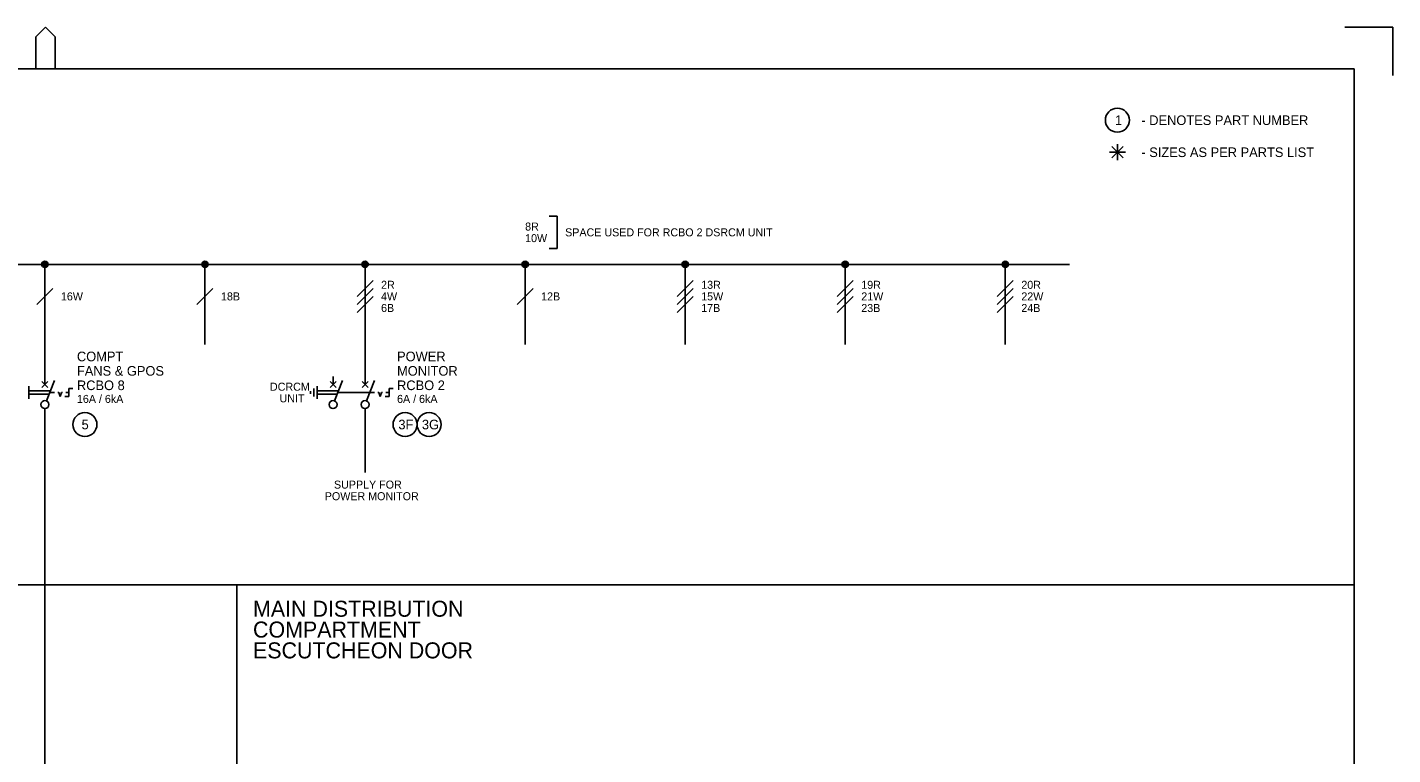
# Model space of a CAD drawing. Extents: x 0 to 841, y 0 to 594.
# Drawn here: x 414.5 to 841, y 366.9 to 594 of the extents above; entities that cross this region are included whole.
import ezdxf

# ---------------------------------------------------------------- set-up
doc = ezdxf.new("R2010")
doc.units = 0
for name, color, linetype in [('A1BORDER', 7, 'Continuous'), ('Level 1', 7, 'Continuous'), ('Level 10', 7, 'Continuous')]:
    doc.layers.add(name, color=color, linetype=linetype)

msp = doc.modelspace()

# ---------------------------------------------------------------- linework, layer by layer
at = {"layer": 'A1BORDER'}
for p, q in [((417.19, 591), (420.19, 594)), ((423.19, 591), (420.19, 594)), ((826, 594), (841, 594)), ((841, 579), (841, 594)), ((417.19, 581), (417.19, 591)), ((423.19, 581), (423.19, 591)), ((28, 581), (829, 581)), ((829, 581), (829, 15))]:
    msp.add_line(p, q, dxfattribs=at)
at = {"layer": 'Level 1'}
for p, q in [((752.5, 555), (757.5, 555)), ((753.23, 556.77), (756.77, 553.23)), ((753.23, 553.23), (756.77, 556.77)), ((755, 552.5), (755, 557.5)), ((80, 520), (740, 520)), ((420, 520), (420, 485)), ((470, 520), (470, 495)), ((520, 520), (520, 485)), ((570, 520), (570, 495)), ((620, 520), (620, 495)), ((670, 520), (670, 495)), ((720, 520), (720, 495)), ((417.5, 507.5), (422.5, 512.5)), ((467.5, 507.5), (472.5, 512.5)), ((517.5, 510), (522.5, 515)), ((517.5, 507.5), (522.5, 512.5)), ((567.5, 507.5), (572.5, 512.5)), ((617.5, 510), (622.5, 515)), ((617.5, 507.5), (622.5, 512.5)), ((667.5, 510), (672.5, 515)), ((667.5, 507.5), (672.5, 512.5)), ((717.5, 510), (722.5, 515)), ((717.5, 507.5), (722.5, 512.5)), ((517.5, 505), (522.5, 510)), ((617.5, 505), (622.5, 510)), ((667.5, 505), (672.5, 510)), ((717.5, 505), (722.5, 510)), ((419.06, 483.44), (420.94, 481.56)), ((420.94, 483.44), (419.06, 481.56)), ((420, 482.5), (420, 485)), ((420.46, 477.41), (423, 483.75)), ((509.06, 483.44), (510.94, 481.56)), ((510.94, 483.44), (509.06, 481.56)), ((510, 482.5), (510, 485)), ((510.46, 477.41), (513, 483.75)), ((519.06, 483.44), (520.94, 481.56)), ((520.94, 483.44), (519.06, 481.56)), ((520, 482.5), (520, 485)), ((520.46, 477.41), (523, 483.75)), ((415, 480.5), (421.7, 480.5)), ((415, 479.5), (421.3, 479.5)), ((505, 480.5), (511.7, 480.5)), ((505, 479.5), (511.3, 479.5)), ((511.5, 480), (521.5, 480)), ((420, 475), (420, 105)), ((520, 475), (520, 455)), ((829, 420), (28, 420)), ((480, 420), (480, 57))]:
    msp.add_line(p, q, dxfattribs=at)
msp.add_lwpolyline([(577.5, 535), (580, 535), (580, 525), (577.5, 525)], dxfattribs=at)
for centre, radius in [((755, 565), 3.75), ((420, 476.25), 1.25), ((432.5, 470), 3.75), ((510, 476.25), 1.25), ((520, 476.25), 1.25), ((532.5, 470), 3.75), ((540, 470), 3.75)]:
    msp.add_circle(centre, radius, dxfattribs=at)
at = {"layer": 'Level 10'}
for p, q in [((419.08, 520.4), (420.92, 520.4)), ((419.29, 520.7), (420.71, 520.7)), ((420, 521), (420, 521)), ((469.08, 520.4), (470.92, 520.4)), ((469.29, 520.7), (470.71, 520.7)), ((470, 521), (470, 521)), ((519.08, 520.4), (520.92, 520.4)), ((519.29, 520.7), (520.71, 520.7)), ((520, 521), (520, 521)), ((569.08, 520.4), (570.92, 520.4)), ((569.29, 520.7), (570.71, 520.7)), ((570, 521), (570, 521)), ((619.08, 520.4), (620.92, 520.4)), ((619.29, 520.7), (620.71, 520.7)), ((620, 521), (620, 521)), ((669.08, 520.4), (670.92, 520.4)), ((669.29, 520.7), (670.71, 520.7)), ((670, 521), (670, 521)), ((719.08, 520.4), (720.92, 520.4)), ((719.29, 520.7), (720.71, 520.7)), ((720, 521), (720, 521)), ((419.01, 520.1), (420.99, 520.1)), ((419.02, 519.8), (420.98, 519.8)), ((419.13, 519.5), (420.87, 519.5)), ((419.4, 519.2), (420.6, 519.2)), ((469.01, 520.1), (470.99, 520.1)), ((469.02, 519.8), (470.98, 519.8)), ((469.13, 519.5), (470.87, 519.5)), ((469.4, 519.2), (470.6, 519.2)), ((519.01, 520.1), (520.99, 520.1)), ((519.02, 519.8), (520.98, 519.8)), ((519.13, 519.5), (520.87, 519.5)), ((519.4, 519.2), (520.6, 519.2)), ((569.01, 520.1), (570.99, 520.1)), ((569.02, 519.8), (570.98, 519.8)), ((569.13, 519.5), (570.87, 519.5)), ((569.4, 519.2), (570.6, 519.2)), ((619.01, 520.1), (620.99, 520.1)), ((619.02, 519.8), (620.98, 519.8)), ((619.13, 519.5), (620.87, 519.5)), ((619.4, 519.2), (620.6, 519.2)), ((669.01, 520.1), (670.99, 520.1)), ((669.02, 519.8), (670.98, 519.8)), ((669.13, 519.5), (670.87, 519.5)), ((669.4, 519.2), (670.6, 519.2)), ((719.01, 520.1), (720.99, 520.1)), ((719.02, 519.8), (720.98, 519.8)), ((719.13, 519.5), (720.87, 519.5)), ((719.4, 519.2), (720.6, 519.2)), ((415, 482), (415, 478)), ((505, 482), (505, 478)), ((421.5, 480), (423, 480)), ((424, 480), (424.33, 480)), ((424.75, 478.75), (424.33, 480)), ((424.75, 478.75), (425.17, 480)), ((425.5, 480), (425.17, 480)), ((426.25, 478.75), (427.5, 478.75)), ((426.5, 480), (427.5, 480)), ((427.5, 478.75), (427.5, 481.25)), ((427.5, 481.25), (428.75, 481.25)), ((503, 480.4), (503, 479.6)), ((504, 481.2), (504, 478.8)), ((521.5, 480), (523, 480)), ((524, 480), (524.33, 480)), ((524.75, 478.75), (524.33, 480)), ((524.75, 478.75), (525.17, 480)), ((525.5, 480), (525.17, 480)), ((526.25, 478.75), (527.5, 478.75)), ((526.5, 480), (527.5, 480)), ((527.5, 478.75), (527.5, 481.25)), ((527.5, 481.25), (528.75, 481.25))]:
    msp.add_line(p, q, dxfattribs=at)
for centre in [(420, 520), (470, 520), (520, 520), (570, 520), (620, 520), (670, 520), (720, 520)]:
    msp.add_circle(centre, 1, dxfattribs=at)

# ---------------------------------------------------------------- texts
at = {"layer": 'Level 1'}
for s, height, p in [('1', 3, (754.25, 563.5)), ('- DENOTES PART NUMBER', 3, (762.5, 563.5)), ('- SIZES AS PER PARTS LIST', 3, (762.5, 553.5)), ('8R', 2.5, (570, 530.56)), ('10W', 2.5, (570, 526.94)), ('SPACE USED FOR RCBO 2 DSRCM UNIT', 2.5, (582.5, 528.75)), ('2R', 2.5, (525, 512.37)), ('13R', 2.5, (625, 512.37)), ('19R', 2.5, (675, 512.37)), ('20R', 2.5, (725, 512.37)), ('16W', 2.5, (425, 508.75)), ('18B', 2.5, (475, 508.75)), ('4W', 2.5, (525, 508.75)), ('6B', 2.5, (525, 505.13)), ('12B', 2.5, (575, 508.75)), ('15W', 2.5, (625, 508.75)), ('17B', 2.5, (625, 505.13)), ('21W', 2.5, (675, 508.75)), ('23B', 2.5, (675, 505.13)), ('22W', 2.5, (725, 508.75)), ('24B', 2.5, (725, 505.13)), ('COMPT', 3, (430, 489.75)), ('POWER', 3, (530, 489.75)), ('FANS & GPOS', 3, (430, 485.25)), ('MONITOR', 3, (530, 485.25)), ('RCBO 8', 3, (430, 480.75)), ('DCRCM', 2.5, (490.29, 480.56)), ('RCBO 2', 3, (530, 480.75)), ('16A / 6kA', 2.5, (430, 476.75)), ('UNIT', 2.5, (493.28, 476.94)), ('6A / 6kA', 2.5, (530, 476.75)), ('5', 3, (431.45, 468.5)), ('3F', 3, (530.41, 468.5)), ('3G', 3, (537.76, 468.5)), ('SUPPLY FOR', 2.5, (510.29, 450)), ('POWER MONITOR', 2.5, (507.42, 446.38)), ('MAIN DISTRIBUTION', 5, (485, 410)), ('COMPARTMENT', 5, (485, 403.5)), ('ESCUTCHEON DOOR', 5, (485, 397))]:
    msp.add_text(s, height=height, dxfattribs=at).set_placement(p)

doc.saveas('drawing.dxf')
